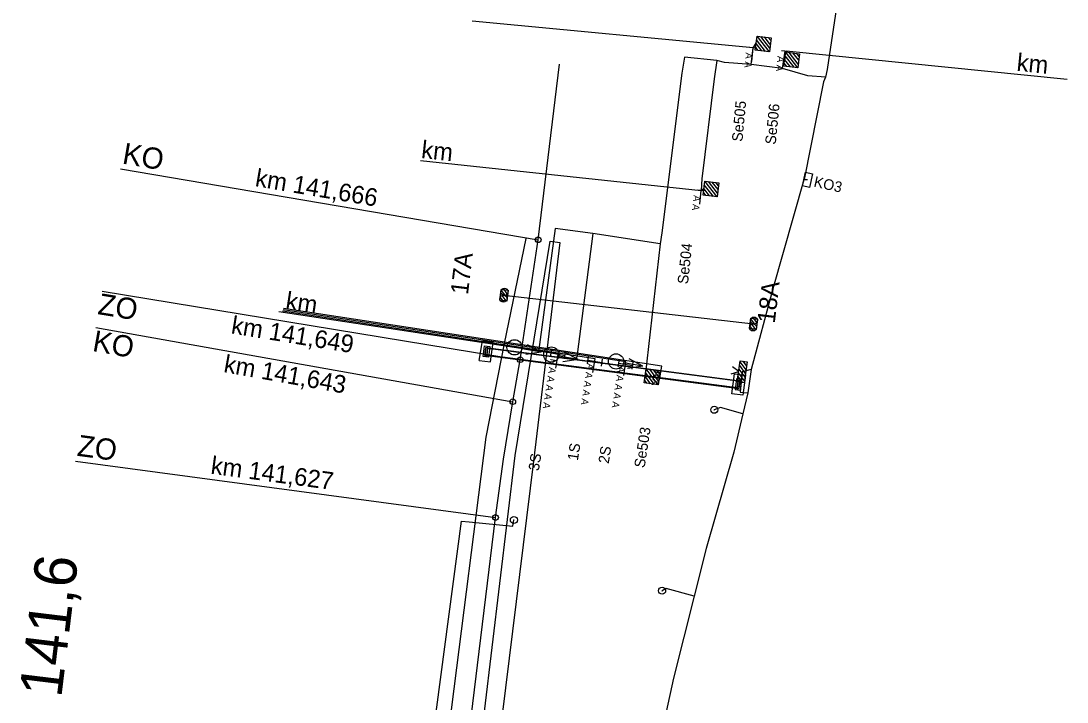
# Model space of a CAD drawing. Extents: x -598638 to -597933, y -1164002 to -1161904.
# Drawn here: x -598543.3 to -598395.1, y -1162942.3 to -1162845.8 of the extents above; entities that cross this region are included whole.
import ezdxf

# ---------------------------------------------------------------- set-up
doc = ezdxf.new("R2010")
doc.units = 0
for name, color, linetype in [('Vrstva 1', 7, 'Continuous'), ('Vrstva 11', 7, 'Continuous'), ('Vrstva 12', 7, 'Continuous'), ('Vrstva 25', 7, 'Continuous'), ('Vrstva 26', 7, 'Continuous'), ('Vrstva 28', 7, 'Continuous'), ('Vrstva 3', 7, 'Continuous'), ('Vrstva 31', 7, 'Continuous'), ('Vrstva 35', 7, 'Continuous'), ('Vrstva 4', 7, 'Continuous'), ('Vrstva 51', 7, 'Continuous'), ('Vrstva 6', 7, 'Continuous'), ('Vrstva 7', 7, 'Continuous')]:
    doc.layers.add(name, color=color, linetype=linetype)

msp = doc.modelspace()

# ---------------------------------------------------------------- linework, layer by layer
at = {"layer": 'Vrstva 1'}
for p, q in [((-598529.2, -1162866.74), (-598470.05, -1162876.79)), ((-598531.8, -1162884.08), (-598472.59, -1162893.78)), ((-598532.72, -1162889.2), (-598473.65, -1162899.73)), ((-598535.56, -1162908.16), (-598476.09, -1162916.14))]:
    msp.add_line(p, q, dxfattribs=at)
for points in [[(-598470.05, -1162876.79), (-598467.01, -1162851.88)], [(-598472.59, -1162893.78), (-598470.05, -1162876.79)], [(-598473.65, -1162899.73), (-598472.59, -1162893.78)], [(-598476.09, -1162916.14), (-598474.98, -1162907.86), (-598473.65, -1162899.73)], [(-598490.92, -1163037.88), (-598486.08, -1162998.23), (-598481.36, -1162959.57), (-598476.09, -1162916.14)]]:
    msp.add_lwpolyline(points, dxfattribs=at)
for centre in [(-598470.05, -1162876.79), (-598472.59, -1162893.78), (-598473.65, -1162899.73), (-598476.09, -1162916.14)]:
    msp.add_circle(centre, 0.4, dxfattribs=at)
at = {"layer": 'Vrstva 11'}
for p, q in [((-598474.74, -1162884.65), (-598475.27, -1162883.93)), ((-598474.57, -1162885.43), (-598475.13, -1162884.67)), ((-598474.42, -1162884.44), (-598474.98, -1162883.68)), ((-598474.9, -1162884.65), (-598439.56, -1162888.72)), ((-598474.89, -1162885.64), (-598475.42, -1162884.92)), ((-598439.55, -1162889.71), (-598440.08, -1162888.99)), ((-598439.4, -1162888.72), (-598439.93, -1162888)), ((-598439.23, -1162889.5), (-598439.79, -1162888.74)), ((-598439.08, -1162888.51), (-598439.64, -1162887.75))]:
    msp.add_line(p, q, dxfattribs=at)
for centre in [(-598474.97, -1162885.14), (-598474.97, -1162885.14), (-598474.83, -1162884.16), (-598474.83, -1162884.16), (-598439.63, -1162889.21), (-598439.63, -1162889.21), (-598439.49, -1162888.23), (-598439.49, -1162888.23)]:
    msp.add_circle(centre, 0.5, dxfattribs=at)
at = {"layer": 'Vrstva 12'}
for p, q in [((-598475.46, -1162885.34), (-598475.27, -1162883.85)), ((-598475.27, -1162883.85), (-598474.32, -1162883.92)), ((-598474.32, -1162883.92), (-598474.49, -1162885.47)), ((-598474.49, -1162885.47), (-598475.46, -1162885.34)), ((-598440.11, -1162889.37), (-598439.93, -1162887.89)), ((-598439.93, -1162887.89), (-598438.99, -1162888.02)), ((-598438.99, -1162888.02), (-598439.18, -1162889.49)), ((-598439.18, -1162889.49), (-598440.11, -1162889.37)), ((-598478.39, -1162893.88), (-598477.96, -1162891.1)), ((-598477.96, -1162891.1), (-598476.42, -1162891.31)), ((-598477.85, -1162893.34), (-598477.66, -1162891.82)), ((-598477.66, -1162891.82), (-598476.92, -1162891.92)), ((-598476.92, -1162891.92), (-598477.11, -1162893.43)), ((-598476.81, -1162894.1), (-598476.42, -1162891.31)), ((-598477.11, -1162893.43), (-598477.85, -1162893.34)), ((-598478.39, -1162893.88), (-598476.81, -1162894.1)), ((-598442.63, -1162898.6), (-598442.26, -1162895.8)), ((-598442.26, -1162895.8), (-598440.67, -1162895.98)), ((-598441.94, -1162896.47), (-598442.13, -1162898)), ((-598441.21, -1162896.56), (-598441.94, -1162896.47)), ((-598441.41, -1162898.09), (-598441.21, -1162896.56)), ((-598440.67, -1162895.98), (-598441.05, -1162898.81)), ((-598442.13, -1162898), (-598441.41, -1162898.09)), ((-598441.05, -1162898.81), (-598442.63, -1162898.6))]:
    msp.add_line(p, q, dxfattribs=at)
at = {"layer": 'Vrstva 25'}
msp.add_line((-598473.55, -1162916.5), (-598473.45, -1162916.5), dxfattribs=at)
msp.add_lwpolyline([(-598432.18, -1162867.21), (-598431.2, -1162867.43), (-598431.64, -1162869.38), (-598432.62, -1162869.16), (-598432.18, -1162867.21)], dxfattribs=at)
msp.add_circle((-598473.49, -1162916.5), 0.5, dxfattribs=at)
at = {"layer": 'Vrstva 26'}
msp.add_lwpolyline([(-598493.83, -1163014.28), (-598480.89, -1162916.65), (-598479.84, -1162916.78), (-598473.65, -1162917.37), (-598473.49, -1162916.5)], dxfattribs=at)
at = {"layer": 'Vrstva 28'}
for p, q in [((-598431.91, -1162868.29), (-598432.42, -1162868.28)), ((-598440.67, -1162895.74), (-598441.51, -1162894.61)), ((-598440.59, -1162895.22), (-598441.43, -1162894.08)), ((-598440.51, -1162894.69), (-598441.02, -1162894.01)), ((-598440.44, -1162894.17), (-598440.49, -1162894.09)), ((-598441.11, -1162897.03), (-598441.74, -1162896.18)), ((-598440.83, -1162896.79), (-598441.67, -1162895.66)), ((-598440.75, -1162896.27), (-598441.59, -1162895.13)), ((-598441.64, -1162896.95), (-598441.82, -1162896.71)), ((-598445.16, -1162900.88), (-598445.06, -1162900.88)), ((-598452.55, -1162926.52), (-598452.45, -1162926.52))]:
    msp.add_line(p, q, dxfattribs=at)
for points in [[(-598427.5, -1162841.9), (-598429.1, -1162852.63), (-598429.36, -1162853.75), (-598429.62, -1162854.41), (-598432.4, -1162868.22), (-598432.42, -1162868.28), (-598436.81, -1162883.74), (-598439.88, -1162895.16), (-598440.37, -1162898.5), (-598441.05, -1162901.43), (-598442.32, -1162906.88), (-598446.26, -1162920.53), (-598447.96, -1162927.3), (-598450.89, -1162938.91), (-598454, -1162953.23)], [(-598439.87, -1162851.92), (-598439.58, -1162849.57), (-598439.18, -1162848.91)], [(-598435.44, -1162852.51), (-598435.09, -1162850.06), (-598435.14, -1162851.17)], [(-598429.36, -1162853.75), (-598431.87, -1162853.56), (-598435.44, -1162852.51), (-598439.87, -1162851.92), (-598443.68, -1162851.68), (-598444.74, -1162851.39), (-598449.32, -1162850.9), (-598449.71, -1162853.19), (-598452.54, -1162875.82), (-598452.77, -1162877.34), (-598454.91, -1162896.05)], [(-598444.74, -1162851.39), (-598445.12, -1162853.97), (-598446.85, -1162868.15), (-598446.96, -1162869.79), (-598446.58, -1162869.46)], [(-598452.77, -1162877.34), (-598462.31, -1162875.89), (-598467.65, -1162875.19), (-598470.02, -1162892.68), (-598469.62, -1162892.71)], [(-598462.31, -1162875.89), (-598464.53, -1162893.06), (-598464.69, -1162893.77), (-598464.4, -1162893.74)], [(-598442.7, -1162895.78), (-598441.64, -1162895.44), (-598442.55, -1162894.79)], [(-598441.85, -1162896.92), (-598441.42, -1162893.95), (-598440.43, -1162894.1), (-598440.86, -1162897.07), (-598441.85, -1162896.92)], [(-598439.88, -1162895.16), (-598441.14, -1162895.51), (-598441.45, -1162898.39), (-598440.37, -1162898.5)], [(-598441.05, -1162901.43), (-598444.24, -1162900.55), (-598445.11, -1162900.88)], [(-598447.96, -1162927.3), (-598451.93, -1162926.21), (-598452.5, -1162926.52)]]:
    msp.add_lwpolyline(points, dxfattribs=at)
msp.add_lwpolyline([(-598441.85, -1162896.92), (-598441.42, -1162893.95), (-598440.43, -1162894.1), (-598440.86, -1162897.07)], close=True, dxfattribs=at)
for centre in [(-598445.11, -1162900.88), (-598452.5, -1162926.52)]:
    msp.add_circle(centre, 0.5, dxfattribs=at)
at = {"layer": 'Vrstva 3'}
for p, q in [((-598438.37, -1162850.01), (-598439.18, -1162848.97)), ((-598437.84, -1162850.08), (-598439.12, -1162848.44)), ((-598437.31, -1162850.14), (-598439.05, -1162847.92)), ((-598437.25, -1162849.62), (-598438.53, -1162847.98)), ((-598437.18, -1162849.09), (-598438, -1162848.04)), ((-598437.12, -1162848.56), (-598437.48, -1162848.11)), ((-598438.89, -1162849.95), (-598439.25, -1162849.49)), ((-598433.27, -1162852.4), (-598435.02, -1162850.17)), ((-598433.21, -1162851.88), (-598434.49, -1162850.24)), ((-598433.15, -1162851.35), (-598433.96, -1162850.3)), ((-598433.08, -1162850.82), (-598433.44, -1162850.37)), ((-598434.85, -1162852.21), (-598435.21, -1162851.75)), ((-598434.33, -1162852.27), (-598435.15, -1162851.23)), ((-598433.8, -1162852.34), (-598435.08, -1162850.7)), ((-598445.77, -1162870.57), (-598446.58, -1162869.52)), ((-598445.24, -1162870.63), (-598446.52, -1162869)), ((-598444.71, -1162870.7), (-598446.45, -1162868.47)), ((-598444.65, -1162870.17), (-598445.93, -1162868.53)), ((-598444.58, -1162869.64), (-598445.4, -1162868.6)), ((-598444.52, -1162869.12), (-598444.88, -1162868.66)), ((-598446.29, -1162870.5), (-598446.65, -1162870.05)), ((-598469.62, -1162892.71), (-598471.54, -1162891.67)), ((-598469.62, -1162892.71), (-598472.34, -1162892.23)), ((-598469.62, -1162892.71), (-598471.78, -1162893.03)), ((-598468.3, -1162893.33), (-598468.13, -1162892.34)), ((-598468.21, -1162892.83), (-598466.25, -1162893.19)), ((-598464.4, -1162893.74), (-598467.12, -1162893.26)), ((-598466.33, -1162893.68), (-598466.16, -1162892.69)), ((-598464.4, -1162893.74), (-598466.32, -1162892.7)), ((-598463.07, -1162894.33), (-598462.9, -1162893.34)), ((-598464.4, -1162893.74), (-598466.56, -1162894.06)), ((-598462.98, -1162893.83), (-598461.02, -1162894.19)), ((-598461.1, -1162894.68), (-598460.93, -1162893.69)), ((-598458.72, -1162894.76), (-598458.55, -1162893.77)), ((-598458.63, -1162894.26), (-598456.67, -1162894.62)), ((-598455.23, -1162894.71), (-598457.95, -1162894.23)), ((-598455.23, -1162894.71), (-598457.39, -1162895.03)), ((-598455.23, -1162894.71), (-598457.15, -1162893.67)), ((-598456.75, -1162895.11), (-598456.58, -1162894.12)), ((-598453.08, -1162897.33), (-598454.77, -1162895.07)), ((-598454.13, -1162897.18), (-598454.92, -1162896.11)), ((-598453.6, -1162897.25), (-598454.85, -1162895.59)), ((-598453, -1162896.8), (-598454.25, -1162895.14)), ((-598452.93, -1162896.28), (-598453.72, -1162895.21)), ((-598452.85, -1162895.75), (-598453.2, -1162895.29)), ((-598454.65, -1162897.1), (-598455, -1162896.64))]:
    msp.add_line(p, q, dxfattribs=at)
for points in [[(-598439.3, -1162849.9), (-598439.05, -1162847.92), (-598437.07, -1162848.16), (-598437.31, -1162850.14)], [(-598439.3, -1162849.9), (-598439.05, -1162847.92), (-598437.07, -1162848.16), (-598437.31, -1162850.14)], [(-598435.26, -1162852.16), (-598435.02, -1162850.17), (-598433.03, -1162850.42), (-598433.27, -1162852.4)], [(-598435.26, -1162852.16), (-598435.02, -1162850.17), (-598433.03, -1162850.42), (-598433.27, -1162852.4)], [(-598446.7, -1162870.45), (-598446.45, -1162868.47), (-598444.47, -1162868.71), (-598444.71, -1162870.7)], [(-598446.7, -1162870.45), (-598446.45, -1162868.47), (-598444.47, -1162868.71), (-598444.71, -1162870.7)], [(-598455.06, -1162897.04), (-598454.77, -1162895.07), (-598452.79, -1162895.35), (-598453.08, -1162897.33)], [(-598455.06, -1162897.04), (-598454.77, -1162895.07), (-598452.79, -1162895.35), (-598453.08, -1162897.33)]]:
    msp.add_lwpolyline(points, close=True, dxfattribs=at)
for points in [[(-598439.3, -1162849.9), (-598439.05, -1162847.92), (-598437.07, -1162848.16), (-598437.31, -1162850.14), (-598439.3, -1162849.9)], [(-598439.3, -1162849.9), (-598439.05, -1162847.92), (-598437.07, -1162848.16), (-598437.31, -1162850.14), (-598439.3, -1162849.9)], [(-598435.26, -1162852.16), (-598435.02, -1162850.17), (-598433.03, -1162850.42), (-598433.27, -1162852.4), (-598435.26, -1162852.16)], [(-598435.26, -1162852.16), (-598435.02, -1162850.17), (-598433.03, -1162850.42), (-598433.27, -1162852.4), (-598435.26, -1162852.16)], [(-598446.7, -1162870.45), (-598446.45, -1162868.47), (-598444.47, -1162868.71), (-598444.71, -1162870.7), (-598446.7, -1162870.45)], [(-598446.7, -1162870.45), (-598446.45, -1162868.47), (-598444.47, -1162868.71), (-598444.71, -1162870.7), (-598446.7, -1162870.45)], [(-598455.06, -1162897.04), (-598454.77, -1162895.07), (-598452.79, -1162895.35), (-598453.08, -1162897.33), (-598455.06, -1162897.04)], [(-598455.06, -1162897.04), (-598454.77, -1162895.07), (-598452.79, -1162895.35), (-598453.08, -1162897.33), (-598455.06, -1162897.04)]]:
    msp.add_lwpolyline(points, dxfattribs=at)
for centre in [(-598473.4, -1162892.03), (-598468.19, -1162893.06), (-598459.02, -1162894.03)]:
    msp.add_circle(centre, 1.08, dxfattribs=at)
at = {"layer": 'Vrstva 31'}
msp.add_lwpolyline([(-598427.5, -1162841.9), (-598429.1, -1162852.63), (-598429.36, -1162853.75), (-598429.62, -1162854.41), (-598432.4, -1162868.22), (-598432.42, -1162868.28), (-598436.81, -1162883.74), (-598439.88, -1162895.16), (-598440.37, -1162898.5), (-598441.05, -1162901.43), (-598442.32, -1162906.88), (-598446.26, -1162920.53), (-598447.96, -1162927.3), (-598450.89, -1162938.91), (-598454, -1162953.23)], dxfattribs=at)
at = {"layer": 'Vrstva 35'}
msp.add_lwpolyline([(-598429.36, -1162853.75), (-598431.87, -1162853.56), (-598435.44, -1162852.51), (-598439.87, -1162851.92), (-598443.68, -1162851.68), (-598444.74, -1162851.39), (-598449.32, -1162850.9)], dxfattribs=at)
at = {"layer": 'Vrstva 4'}
msp.add_lwpolyline([(-598498.34, -1163129.68), (-598496.71, -1163105.39), (-598496.44, -1163083.97), (-598496.41, -1163066.1), (-598495.03, -1163049.33), (-598491.68, -1163019.45), (-598487.03, -1162981.73), (-598482.3, -1162943.02), (-598477.41, -1162904.76), (-598474.84, -1162891.5), (-598471.73, -1162876.6)], dxfattribs=at)
at = {"layer": 'Vrstva 51'}
msp.add_lwpolyline([(-598491.72, -1163069.8), (-598490.59, -1163049.57), (-598487.01, -1163019.97), (-598482.28, -1162981.39), (-598477.64, -1162943.65), (-598473.3, -1162907.34), (-598468.37, -1162876.99), (-598466.96, -1162877.17), (-598470.72, -1162908.17), (-598475.15, -1162944.09), (-598479.77, -1162981.58), (-598484.51, -1163020.39), (-598490.47, -1163069.86), (-598491.72, -1163069.8)], dxfattribs=at)
at = {"layer": 'Vrstva 6'}
for p, q in [((-598439.58, -1162849.57), (-598479.4, -1162845.79)), ((-598439.08, -1162849.62), (-598440.08, -1162849.53)), ((-598439.77, -1162851.54), (-598439.58, -1162849.57)), ((-598434.59, -1162850.11), (-598435.59, -1162850.01)), ((-598435.28, -1162852.03), (-598435.09, -1162850.06)), ((-598395.14, -1162854.05), (-598434.94, -1162850.07)), ((-598486.73, -1162865.53), (-598446.96, -1162869.79)), ((-598446.46, -1162869.85), (-598447.46, -1162869.74)), ((-598447.17, -1162871.76), (-598446.96, -1162869.79)), ((-598467.23, -1162893.01), (-598506.78, -1162886.99)), ((-598462, -1162893.65), (-598506.26, -1162886.92)), ((-598457.63, -1162894.07), (-598506.17, -1162886.69)), ((-598452.55, -1162894.68), (-598506.13, -1162886.53)), ((-598477.6, -1162893.18), (-598477.46, -1162892.03)), ((-598477.46, -1162892.04), (-598477.6, -1162893.19)), ((-598477.46, -1162892.06), (-598477.6, -1162893.15)), ((-598477.46, -1162892.03), (-598477.46, -1162892.04)), ((-598477.46, -1162892.03), (-598477.16, -1162892.07)), ((-598477.46, -1162892.04), (-598477.16, -1162892.07)), ((-598477.46, -1162892.06), (-598441.48, -1162896.76)), ((-598477.3, -1162893.22), (-598477.16, -1162892.07)), ((-598477.3, -1162893.22), (-598477.16, -1162892.07)), ((-598477.16, -1162892.07), (-598477.16, -1162892.07)), ((-598477.6, -1162893.15), (-598441.62, -1162897.84)), ((-598477.6, -1162893.19), (-598477.6, -1162893.18)), ((-598477.6, -1162893.18), (-598477.3, -1162893.22)), ((-598477.3, -1162893.22), (-598477.6, -1162893.19)), ((-598477.3, -1162893.22), (-598477.3, -1162893.22)), ((-598477.29, -1162893.16), (-598477.16, -1162892.17)), ((-598441.89, -1162897.76), (-598477.29, -1162893.16)), ((-598477.16, -1162892.17), (-598441.77, -1162896.76)), ((-598467.53, -1162894.97), (-598467.23, -1162893.01)), ((-598462.3, -1162895.61), (-598462, -1162893.65)), ((-598457.93, -1162896.03), (-598457.63, -1162894.07)), ((-598452.85, -1162896.64), (-598452.55, -1162894.68)), ((-598441.74, -1162896.69), (-598441.9, -1162897.84)), ((-598441.9, -1162897.84), (-598441.61, -1162897.88)), ((-598441.9, -1162897.84), (-598441.89, -1162897.84)), ((-598441.74, -1162896.69), (-598441.89, -1162897.84)), ((-598441.77, -1162896.76), (-598441.89, -1162897.76)), ((-598441.61, -1162897.88), (-598441.89, -1162897.84)), ((-598441.46, -1162896.74), (-598441.74, -1162896.69)), ((-598441.74, -1162896.69), (-598441.74, -1162896.69)), ((-598441.74, -1162896.69), (-598441.45, -1162896.73)), ((-598441.48, -1162896.76), (-598441.62, -1162897.84)), ((-598441.45, -1162896.73), (-598441.61, -1162897.88)), ((-598441.61, -1162897.88), (-598441.46, -1162896.74)), ((-598441.61, -1162897.88), (-598441.61, -1162897.88)), ((-598441.45, -1162896.73), (-598441.46, -1162896.74))]:
    msp.add_line(p, q, dxfattribs=at)

# ---------------------------------------------------------------- texts
at = {"layer": 'Vrstva 1'}
for s, height, rotation, p in [('KO', 3, 350.3502, (-598529.07, -1162865.97)), ('km 141,666', 2.5, 350.3749, (-598510.24, -1162869.17)), ('ZO', 3, 350.699, (-598532.54, -1162887.31)), ('km 141,649', 2.5, 350.7237, (-598513.64, -1162890.04)), ('KO', 3, 349.8883, (-598533.3, -1162892.53)), ('km 141,643', 2.5, 349.913, (-598514.7, -1162895.53)), ('ZO', 3, 352.3497, (-598535.45, -1162907.39)), ('km 141,627', 2.5, 352.3743, (-598516.52, -1162909.93))]:
    msp.add_text(s, height=height, rotation=rotation, dxfattribs=at).set_placement(p)
at = {"layer": 'Vrstva 11'}
for s, p in [('17A', (-598480, -1162884.65)), ('18A', (-598436.55, -1162888.71))]:
    msp.add_text(s, height=2.5, rotation=83.2508, dxfattribs=at).set_placement(p)
at = {"layer": 'Vrstva 25'}
msp.add_text('KO3', height=1.5, rotation=347.309, dxfattribs=at).set_placement((-598431.11, -1162869.23))
at = {"layer": 'Vrstva 6'}
for s, height, rotation, p in [('  A A', 1, 264.5732, (-598440.58, -1162849.48)), ('km ', 2.5, 354.2942, (-598402.36, -1162852.83)), ('  A A', 1, 264.5732, (-598436.09, -1162849.97)), ('Se505', 1.5, 84.5732, (-598441.13, -1162862.93)), ('Se506', 1.5, 84.2942, (-598436.42, -1162863.34)), ('km ', 2.5, 353.8738, (-598486.69, -1162865.19)), ('  A A', 1, 263.8738, (-598447.95, -1162869.69)), ('Se504', 1.5, 83.8738, (-598448.84, -1162883.12)), ('km ', 2.5, 351.3498, (-598505.93, -1162886.59)), ('km ', 2.5, 351.3498, (-598505.93, -1162886.59)), ('km ', 2.5, 351.3498, (-598505.93, -1162886.59)), ('km ', 2.5, 351.3498, (-598505.93, -1162886.59)), ('  F A A A A A', 1, 261.3498, (-598468.22, -1162892.86)), ('  A A A A A', 1, 261.3498, (-598462.99, -1162893.5)), ('  A A A A A', 1, 261.3498, (-598458.62, -1162893.92)), ('  A A', 1, 261.3498, (-598453.54, -1162894.53)), ('Se503', 1.5, 81.3498, (-598454.98, -1162909.18)), ('1S', 1.5, 81.3498, (-598464.43, -1162908.15)), ('2S', 1.5, 81.3498, (-598460.06, -1162908.57)), ('3S', 1.5, 81.3498, (-598469.96, -1162909.6))]:
    msp.add_text(s, height=height, rotation=rotation, dxfattribs=at).set_placement(p)
at = {"layer": 'Vrstva 7'}
msp.add_text('141,6', height=6, rotation=83.0815, dxfattribs=at).set_placement((-598537.6, -1162941.79))

doc.saveas('drawing.dxf')
